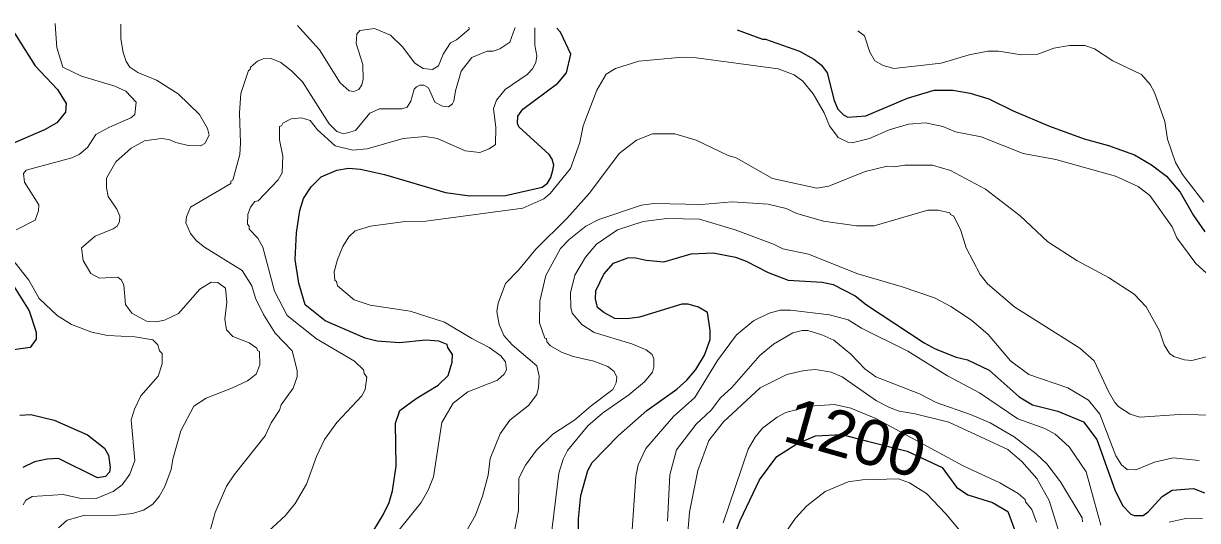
# Model space of a CAD drawing. Extents: x 598.3 to 623.2, y 6902.2 to 6930.1.
# Drawn here: x 609.703 to 611.773, y 6929.108 to 6929.984 of the extents above; entities that cross this region are included whole.
import ezdxf
from ezdxf.enums import TextEntityAlignment as Align

# ---------------------------------------------------------------- set-up
doc = ezdxf.new("R2010")
doc.units = 0
doc.header["$LTSCALE"] = 0.032
doc.layers.add('1', color=7, linetype='Continuous', lineweight=25)
doc.layers.add('2', color=7, linetype='Continuous', lineweight=13)
doc.layers.add('61', color=7, linetype='Continuous')

msp = doc.modelspace()

# ---------------------------------------------------------------- linework, layer by layer
at = {"layer": '1'}
for points in [[(609.6802, 6929.9779), (609.7233, 6929.9089), (609.763, 6929.8671), (609.7779, 6929.8425), (609.7771, 6929.8275), (609.7615, 6929.8085), (609.7397, 6929.7963), (609.6771, 6929.7691)], [(610.3103, 6929.0743), (610.3372, 6929.1179), (610.3473, 6929.1399), (610.3536, 6929.1605), (610.3601, 6929.2038), (610.3585, 6929.2792), (610.3663, 6929.302), (610.3951, 6929.3231), (610.4342, 6929.3461), (610.4514, 6929.3635), (610.4587, 6929.3868), (610.4594, 6929.4001), (610.4507, 6929.4128), (610.4498, 6929.4181), (610.4352, 6929.424), (610.4122, 6929.4257), (610.3656, 6929.421), (610.3263, 6929.4241), (610.3053, 6929.4289), (610.2348, 6929.4596), (610.1996, 6929.4881), (610.1884, 6929.5261), (610.182, 6929.5679), (610.1841, 6929.6148), (610.1901, 6929.6543), (610.1966, 6929.675), (610.2098, 6929.6956), (610.2278, 6929.7136), (610.2551, 6929.7253), (610.2758, 6929.7284), (610.2972, 6929.7268), (610.3392, 6929.7175), (610.4471, 6929.6856), (610.4898, 6929.6799), (610.5524, 6929.6807), (610.6174, 6929.6953), (610.6269, 6929.7021), (610.6327, 6929.7121), (610.636, 6929.7249), (610.6381, 6929.734), (610.6349, 6929.7443), (610.6294, 6929.7529), (610.576, 6929.8013), (610.5739, 6929.8081), (610.5746, 6929.8205), (610.5833, 6929.8326), (610.6446, 6929.8781), (610.6604, 6929.8964), (610.6675, 6929.9295), (610.6493, 6929.9684), (610.6431, 6929.9755)], [(610.9612, 6929.9726), (611.0055, 6929.9557), (611.0111, 6929.9558), (611.0706, 6929.9345), (611.0964, 6929.9207), (611.1097, 6929.9103), (611.1194, 6929.8966), (611.1319, 6929.8479), (611.1386, 6929.8324), (611.1482, 6929.8226), (611.1558, 6929.8184), (611.188, 6929.821), (611.2612, 6929.8521), (611.3084, 6929.866), (611.3414, 6929.866), (611.3716, 6929.8605), (611.4045, 6929.8506), (611.4475, 6929.8297), (611.5114, 6929.8028), (611.5726, 6929.7802), (611.6157, 6929.7683), (611.6613, 6929.752), (611.6911, 6929.7348), (611.7177, 6929.7145), (611.742, 6929.6862), (611.7652, 6929.645), (611.7851, 6929.6164)], [(610.6822, 6928.9996), (610.6814, 6929.1107), (610.6854, 6929.1518), (610.6977, 6929.1961), (610.7053, 6929.21), (610.752, 6929.2576), (610.802, 6929.3018), (610.8549, 6929.3392), (610.8722, 6929.3551), (610.888, 6929.3742), (610.9036, 6929.3991), (610.9136, 6929.4271), (610.9136, 6929.4433), (610.9087, 6929.4742), (610.8926, 6929.4839), (610.8748, 6929.4888), (610.8635, 6929.4888), (610.7887, 6929.4661), (610.7672, 6929.463), (610.7453, 6929.4638), (610.726, 6929.4742), (610.7148, 6929.4831), (610.7114, 6929.4983), (610.7117, 6929.5125), (610.7258, 6929.542), (610.7432, 6929.5611), (610.768, 6929.5706), (610.7793, 6929.5714), (610.8007, 6929.5665)], [(610.8007, 6929.5665), (610.8319, 6929.5634), (610.8797, 6929.5779), (610.9188, 6929.5795), (610.9581, 6929.572), (610.9771, 6929.5648), (611.0157, 6929.5447), (611.0507, 6929.5316), (611.1109, 6929.5278), (611.1303, 6929.5237), (611.1689, 6929.5038), (611.1889, 6929.488), (611.2909, 6929.4208), (611.3103, 6929.4103), (611.3473, 6929.3958), (611.3673, 6929.3908), (611.4053, 6929.3727), (611.4579, 6929.3258), (611.4817, 6929.3117), (611.5264, 6929.3008), (611.5718, 6929.2816), (611.5953, 6929.2508), (611.627, 6929.1621), (611.6405, 6929.1346), (611.6551, 6929.1193), (611.6609, 6929.1165), (611.6767, 6929.1168), (611.6853, 6929.1232), (611.71, 6929.1503), (611.7278, 6929.1616), (611.7653, 6929.1642), (611.7847, 6929.1569)], [(609.6834, 6929.5242), (609.7132, 6929.4775), (609.725, 6929.44), (609.7253, 6929.4276), (609.7148, 6929.4128), (609.6855, 6929.4088)], [(609.6962, 6929.2937), (609.7159, 6929.2945), (609.7569, 6929.2848), (609.8158, 6929.2591), (609.846, 6929.2355), (609.8525, 6929.223), (609.8557, 6929.2021), (609.8546, 6929.193), (609.8472, 6929.1857), (609.8336, 6929.183), (609.7645, 6929.2174), (609.7446, 6929.2162), (609.7221, 6929.2112), (609.7018, 6929.2011)], [(610.8897, 6928.9067), (610.9662, 6929.1082), (611.0002, 6929.1794), (611.031, 6929.2207), (611.0663, 6929.2429), (611.0989, 6929.2572), (611.1455, 6929.2594), (611.1906, 6929.2479), (611.2607, 6929.2301), (611.3226, 6929.2013), (611.3479, 6929.1666), (611.3677, 6929.1532), (611.411, 6929.1398), (611.4382, 6929.1237), (611.4576, 6929.0716)]]:
    msp.add_lwpolyline(points, dxfattribs=at)
at = {"layer": '2'}
for points in [[(609.7076, 6929.725), (609.7881, 6929.7467), (609.8013, 6929.7526), (609.8156, 6929.7653), (609.8302, 6929.7878), (609.8544, 6929.8011), (609.8919, 6929.8174), (609.8994, 6929.8233), (609.9016, 6929.8452), (609.8833, 6929.8644), (609.8637, 6929.8729), (609.805, 6929.8908), (609.7724, 6929.9067), (609.7615, 6929.9411), (609.7595, 6929.9738), (609.7589, 6929.9835)], [(609.8727, 6929.6443), (609.8674, 6929.6567), (609.8523, 6929.6788), (609.8493, 6929.6939), (609.8493, 6929.711), (609.8656, 6929.7397), (609.8929, 6929.7641), (609.9164, 6929.777), (609.9455, 6929.781), (609.959, 6929.7794), (609.9712, 6929.7738), (609.993, 6929.7686), (610.0149, 6929.7682), (610.0225, 6929.7722), (610.0304, 6929.787), (610.0272, 6929.7984), (610.0129, 6929.8231), (609.9753, 6929.8598), (609.9376, 6929.8837), (609.9046, 6929.8971), (609.8905, 6929.9067), (609.8841, 6929.9164), (609.8784, 6929.9322), (609.8744, 6929.9562), (609.8744, 6929.9803), (609.8744, 6929.9825)], [(610.5695, 6929.9762), (610.5663, 6929.9673), (610.5603, 6929.9506), (610.5429, 6929.9389), (610.5306, 6929.935), (610.5203, 6929.9348), (610.4933, 6929.9238), (610.4743, 6929.8998), (610.4644, 6929.8646), (610.4615, 6929.8469), (610.4593, 6929.8418), (610.4524, 6929.8367), (610.4413, 6929.8378), (610.4283, 6929.845), (610.4166, 6929.8701), (610.4085, 6929.8749), (610.4017, 6929.8748), (610.396, 6929.872), (610.3916, 6929.8677), (610.3859, 6929.8465), (610.3793, 6929.8362), (610.3697, 6929.8329), (610.3302, 6929.8329), (610.3133, 6929.8257), (610.288, 6929.7951), (610.2675, 6929.7892), (610.2551, 6929.793), (610.2418, 6929.807), (610.1945, 6929.8809), (610.1756, 6929.8999), (610.1563, 6929.9145), (610.1398, 6929.9219), (610.1252, 6929.9211), (610.1156, 6929.917), (610.1029, 6929.9068), (610.1024, 6929.9026), (610.0994, 6929.9008), (610.0863, 6929.8603), (610.0839, 6929.8263), (610.0856, 6929.7728), (610.084, 6929.753), (610.072, 6929.7073), (610.0687, 6929.7056), (610.0684, 6929.7017), (609.9976, 6929.6598), (609.9901, 6929.6428), (609.9893, 6929.6325), (609.9972, 6929.6138), (610.008, 6929.6005), (610.0218, 6929.5894), (610.0882, 6929.5485), (610.1057, 6929.5215), (610.1118, 6929.4997), (610.126, 6929.471), (610.1468, 6929.4381), (610.1768, 6929.4066), (610.1852, 6929.3721), (610.1851, 6929.3609), (610.1785, 6929.3413), (610.1574, 6929.3119), (610.1541, 6929.3022), (610.1397, 6929.2798), (610.1291, 6929.2571), (610.0741, 6929.1886), (610.0605, 6929.1683), (610.0407, 6929.1219), (610.0291, 6929.0798)], [(610.1205, 6929.076), (610.1641, 6929.1164), (610.1818, 6929.1381), (610.2016, 6929.1721), (610.2194, 6929.2207), (610.2337, 6929.2508), (610.2551, 6929.2805), (610.2994, 6929.3277), (610.3051, 6929.3389), (610.3082, 6929.3607), (610.3034, 6929.3669), (610.3023, 6929.3733), (610.2867, 6929.3886), (610.2197, 6929.4282), (610.1676, 6929.4692), (610.1455, 6929.5121), (610.1251, 6929.5895), (610.1163, 6929.6054), (610.101, 6929.6211), (610.1008, 6929.6265), (610.0978, 6929.6298), (610.0985, 6929.6473), (610.1032, 6929.6598), (610.1107, 6929.6699), (610.1164, 6929.6712), (610.1517, 6929.708), (610.1592, 6929.7205), (610.16, 6929.7497), (610.1545, 6929.7784), (610.1545, 6929.8019), (610.1576, 6929.8032), (610.1598, 6929.8081), (610.1746, 6929.8158), (610.1929, 6929.8175), (610.208, 6929.8124), (610.2211, 6929.7961), (610.2523, 6929.768), (610.2837, 6929.7601), (610.3088, 6929.7629), (610.3724, 6929.7809), (610.4112, 6929.7844), (610.4327, 6929.7811), (610.4814, 6929.7592), (610.5073, 6929.756), (610.5237, 6929.7626), (610.5348, 6929.7701), (610.5356, 6929.8), (610.5316, 6929.8339), (610.5366, 6929.8485), (610.5523, 6929.8673), (610.5909, 6929.8937), (610.6001, 6929.9038), (610.6061, 6929.9147), (610.6077, 6929.9266), (610.6045, 6929.9452), (610.6045, 6929.9656), (610.6045, 6929.9758)], [(610.1859, 6929.9797), (610.1899, 6929.9753), (610.225, 6929.9371), (610.2614, 6929.8789), (610.2768, 6929.8646), (610.2855, 6929.8637), (610.294, 6929.8673), (610.2994, 6929.8753), (610.3017, 6929.8853), (610.301, 6929.9112), (610.2896, 6929.9481), (610.2904, 6929.9647), (610.2961, 6929.9712), (610.3219, 6929.9745), (610.3498, 6929.9627), (610.3712, 6929.9423), (610.3925, 6929.9137), (610.4073, 6929.9041), (610.4239, 6929.9026), (610.4344, 6929.909), (610.4427, 6929.9295), (610.4558, 6929.9496), (610.4661, 6929.9545), (610.4883, 6929.9734), (610.4882, 6929.9769)], [(611.1737, 6929.9706), (611.1857, 6929.9615), (611.1947, 6929.9328), (611.2034, 6929.918), (611.2184, 6929.9096), (611.2373, 6929.9042), (611.3208, 6929.9136), (611.37, 6929.9284), (611.4029, 6929.9349), (611.4218, 6929.9349), (611.462, 6929.9285), (611.4908, 6929.9293), (611.5195, 6929.9398), (611.5466, 6929.9447), (611.5737, 6929.9446), (611.5907, 6929.9388), (611.6231, 6929.9177), (611.6736, 6929.8935), (611.6893, 6929.8763), (611.6966, 6929.8621), (611.715, 6929.811), (611.7197, 6929.7795), (611.7334, 6929.7389), (611.7458, 6929.7176), (611.7838, 6929.6687)], [(611.8136, 6929.5206), (611.7697, 6929.5605), (611.736, 6929.6057), (611.7279, 6929.6251), (611.6887, 6929.6804), (611.668, 6929.6961), (611.628, 6929.7146), (611.523, 6929.7437), (611.4652, 6929.7545), (611.3911, 6929.7836), (611.346, 6929.7924), (611.3233, 6929.8021), (611.2928, 6929.8086), (611.2632, 6929.8061), (611.2288, 6929.7962), (611.1944, 6929.7807), (611.1636, 6929.773), (611.1558, 6929.7744), (611.1388, 6929.7828), (611.124, 6929.8032), (611.1143, 6929.8259), (611.0952, 6929.8594), (611.0766, 6929.882), (611.0615, 6929.8933), (611.033, 6929.9034), (610.8848, 6929.9235), (610.8646, 6929.9243), (610.7878, 6929.917), (610.7463, 6929.9045), (610.7302, 6929.8945), (610.7137, 6929.8661), (610.6895, 6929.8032), (610.6839, 6929.7741), (610.6673, 6929.7279), (610.6315, 6929.6843), (610.6204, 6929.6749), (610.5832, 6929.658), (610.4119, 6929.6355), (610.3756, 6929.6345), (610.3147, 6929.6264), (610.2874, 6929.6183), (610.2764, 6929.6075), (610.266, 6929.5906), (610.2563, 6929.568), (610.2508, 6929.5461), (610.2516, 6929.5312), (610.2548, 6929.5288), (610.2564, 6929.5215), (610.2858, 6929.4968), (610.3138, 6929.4871), (610.3843, 6929.4767), (610.4453, 6929.4575), (610.4931, 6929.4284), (610.5238, 6929.4126), (610.5444, 6929.3983), (610.5525, 6929.3877), (610.5542, 6929.3734), (610.55, 6929.3657), (610.5385, 6929.3554), (610.4861, 6929.3349), (610.4606, 6929.3149), (610.4406, 6929.2806), (610.4255, 6929.1846), (610.4165, 6929.1616), (610.4039, 6929.1394), (610.3096, 6929.0224)], [(610.7837, 6929.778), (610.8117, 6929.7891), (610.8509, 6929.7891), (610.8886, 6929.7782), (610.9453, 6929.7507), (610.9593, 6929.7469), (611.023, 6929.7102), (611.1013, 6929.6937), (611.1228, 6929.6969), (611.1865, 6929.7228), (611.2257, 6929.7324), (611.2375, 6929.7309), (611.2567, 6929.7341), (611.3055, 6929.7341), (611.3371, 6929.7248), (611.399, 6929.6915), (611.4597, 6929.6446), (611.5086, 6929.5987), (611.5595, 6929.5659), (611.6153, 6929.5359), (611.6606, 6929.5067), (611.6817, 6929.4842), (611.7052, 6929.4422), (611.7137, 6929.4172), (611.7233, 6929.4023), (611.7308, 6929.3966), (611.7494, 6929.3909), (611.7623, 6929.3901), (611.7931, 6929.3974)], [(610.4643, 6929.0551), (610.4998, 6929.1176), (610.5122, 6929.1508), (610.522, 6929.188), (610.5253, 6929.217), (610.543, 6929.2604), (610.5601, 6929.285), (610.5931, 6929.3107), (610.6077, 6929.3297), (610.6109, 6929.3424), (610.6117, 6929.3621), (610.6077, 6929.3803), (610.5641, 6929.4176), (610.5499, 6929.434), (610.5414, 6929.453), (610.5374, 6929.4761), (610.5398, 6929.4907), (610.5527, 6929.5252), (610.5757, 6929.5491), (610.606, 6929.586), (610.6607, 6929.6398), (610.7006, 6929.6845), (610.7529, 6929.7546), (610.7837, 6929.778)], [(609.69, 6929.6201), (609.7236, 6929.637), (609.7293, 6929.6535), (609.7301, 6929.6639), (609.7045, 6929.704), (609.7028, 6929.7193), (609.7076, 6929.725)], [(610.569, 6929.0928), (610.5753, 6929.1256), (610.5761, 6929.1826), (610.5879, 6929.2055), (610.6073, 6929.2317), (610.6363, 6929.2599), (610.6746, 6929.2852), (610.7037, 6929.31), (610.7419, 6929.339), (610.7475, 6929.3506), (610.7486, 6929.3605), (610.744, 6929.3702), (610.733, 6929.3791), (610.7083, 6929.3886), (610.6719, 6929.3967), (610.6512, 6929.4044), (610.6318, 6929.4155), (610.6256, 6929.4226), (610.6247, 6929.4286), (610.6221, 6929.4294), (610.6126, 6929.4563), (610.6132, 6929.4944), (610.6236, 6929.5396), (610.6496, 6929.5869), (610.6646, 6929.6027), (610.6943, 6929.6266), (610.7172, 6929.6381), (610.7923, 6929.6637), (610.8143, 6929.6662), (610.8984, 6929.6646)], [(610.8984, 6929.6646), (610.9522, 6929.6694), (611.0155, 6929.6654), (611.0476, 6929.6574), (611.0663, 6929.6485), (611.1134, 6929.6355), (611.1715, 6929.6272), (611.2025, 6929.6273), (611.2972, 6929.6547), (611.3152, 6929.6548), (611.3358, 6929.6501), (611.3368, 6929.6472), (611.3427, 6929.6441), (611.3554, 6929.619), (611.3649, 6929.5884), (611.3894, 6929.5411), (611.4022, 6929.525), (611.4507, 6929.4835), (611.5649, 6929.4115), (611.5902, 6929.3892), (611.6155, 6929.335), (611.6267, 6929.3159), (611.6339, 6929.3082), (611.6538, 6929.2952), (611.6709, 6929.2898), (611.7405, 6929.2945), (611.8072, 6929.2938)], [(609.7644, 6929.0948), (609.7798, 6929.1086), (609.8112, 6929.1173), (609.8624, 6929.1165), (609.8952, 6929.1205), (609.9142, 6929.1259), (609.9308, 6929.1366), (609.9422, 6929.1502), (609.9518, 6929.1678), (609.9634, 6929.1977), (609.9664, 6929.2159), (609.9804, 6929.2657), (610.0031, 6929.3091), (610.0249, 6929.3237), (610.0716, 6929.3414), (610.098, 6929.3541), (610.1131, 6929.3659), (610.1196, 6929.3821), (610.1188, 6929.4057), (610.1155, 6929.4074), (610.1144, 6929.4114), (610.1005, 6929.4211), (610.0722, 6929.4319), (610.0609, 6929.4439), (610.0581, 6929.4627), (610.0614, 6929.4925), (610.0589, 6929.5175), (610.0456, 6929.5274), (610.0335, 6929.5281), (610.0135, 6929.5153), (609.9762, 6929.4727), (609.9514, 6929.4607), (609.9367, 6929.4581), (609.9197, 6929.4589), (609.894, 6929.4733), (609.8825, 6929.4887), (609.8799, 6929.5226), (609.8755, 6929.5313), (609.8692, 6929.5366), (609.8372, 6929.535), (609.8215, 6929.5428), (609.8082, 6929.566), (609.805, 6929.5885), (609.8291, 6929.6086), (609.8612, 6929.6215), (609.8678, 6929.6265), (609.8719, 6929.634), (609.8727, 6929.6443)], [(611.2503, 6929.5204), (611.1735, 6929.5427), (611.0867, 6929.5771), (611.0415, 6929.5864), (611.0249, 6929.5948), (610.9572, 6929.62), (610.8946, 6929.6386), (610.8371, 6929.6402), (610.7953, 6929.6345), (610.7502, 6929.6199), (610.7132, 6929.595), (610.6934, 6929.572), (610.6749, 6929.5404), (610.6669, 6929.5092), (610.6675, 6929.4834), (610.6702, 6929.4734), (610.6871, 6929.4531), (610.7087, 6929.4392), (610.7756, 6929.4194), (610.8004, 6929.4087), (610.8114, 6929.4001), (610.8142, 6929.3928), (610.8143, 6929.3785), (610.8118, 6929.3693), (610.7979, 6929.3521), (610.7703, 6929.3291), (610.7237, 6929.297), (610.6979, 6929.2747), (610.6618, 6929.2312), (610.6542, 6929.2161), (610.6467, 6929.1914), (610.632, 6929.0712)], [(609.7025, 6929.1358), (609.707, 6929.1438), (609.7184, 6929.1501), (609.7726, 6929.1537), (609.8072, 6929.1463), (609.8313, 6929.147), (609.8612, 6929.1592), (609.8769, 6929.1709), (609.8905, 6929.1893), (609.8994, 6929.2136), (609.893, 6929.2851), (609.8986, 6929.3043), (609.9098, 6929.3274), (609.9405, 6929.3623), (609.9472, 6929.3839), (609.9471, 6929.4019), (609.9425, 6929.4068), (609.9398, 6929.4175), (609.9309, 6929.4265), (609.8992, 6929.4313), (609.851, 6929.4337), (609.8231, 6929.4396), (609.7874, 6929.453), (609.762, 6929.4688), (609.7306, 6929.4989), (609.7121, 6929.5314), (609.6794, 6929.5728)], [(611.7756, 6929.2135), (611.7293, 6929.2184), (611.6966, 6929.2106), (611.6636, 6929.1975), (611.6483, 6929.1978), (611.6386, 6929.2059), (611.6285, 6929.2217), (611.6005, 6929.2954), (611.5805, 6929.3198), (611.5438, 6929.3414), (611.475, 6929.3654), (611.4426, 6929.389), (611.4035, 6929.4354), (611.3741, 6929.4607), (611.3376, 6929.485), (611.309, 6929.5), (611.2503, 6929.5204)], [(610.7744, 6929.0663), (610.7824, 6929.1852), (610.7867, 6929.2058), (610.7997, 6929.2348), (610.849, 6929.2913), (610.8863, 6929.3248), (610.9266, 6929.3901), (610.9597, 6929.4352), (610.9899, 6929.4597), (611.0175, 6929.4734), (611.0365, 6929.4783), (611.0548, 6929.4783), (611.124, 6929.4703), (611.1568, 6929.4612), (611.1803, 6929.447), (611.2621, 6929.4061), (611.3319, 6929.3628), (611.3879, 6929.3328), (611.4555, 6929.2871), (611.5036, 6929.27), (611.5214, 6929.2599), (611.5463, 6929.2375), (611.5765, 6929.1935), (611.6019, 6929.0998)], [(611.5695, 6929.1059), (611.5691, 6929.1125), (611.5307, 6929.1762), (611.5066, 6929.2076), (611.4879, 6929.2255), (611.4494, 6929.2554), (611.407, 6929.2799), (611.3726, 6929.2949), (611.3115, 6929.3159), (611.2823, 6929.3313), (611.2054, 6929.3608), (611.1863, 6929.3749), (611.1611, 6929.401), (611.1312, 6929.4259), (611.1105, 6929.4351), (611.0853, 6929.4427), (611.0754, 6929.4427), (611.0591, 6929.4384), (611.0252, 6929.4183), (611.0009, 6929.3988), (610.9515, 6929.3421), (610.9317, 6929.3238), (610.9149, 6929.3023), (610.8886, 6929.2775), (610.8541, 6929.2323), (610.8425, 6929.1883), (610.8384, 6929.1066)], [(610.8717, 6929.0585), (610.8772, 6929.1227), (610.8919, 6929.1961), (610.9111, 6929.249), (610.9367, 6929.2819), (611.0017, 6929.3414), (611.0485, 6929.3654), (611.0791, 6929.3724), (611.0989, 6929.3739), (611.1269, 6929.3692), (611.1463, 6929.3612), (611.2065, 6929.319), (611.2294, 6929.3069), (611.2466, 6929.3008), (611.275, 6929.2961), (611.3344, 6929.2809), (611.438, 6929.2332), (611.463, 6929.2116), (611.4892, 6929.182), (611.5109, 6929.143), (611.5305, 6929.0809)], [(611.4885, 6929.1049), (611.4804, 6929.1276), (611.4692, 6929.1408), (611.4687, 6929.145), (611.4562, 6929.1557), (611.424, 6929.1746), (611.3591, 6929.2042), (611.2054, 6929.2875), (611.1612, 6929.306), (611.1323, 6929.3123), (611.0885, 6929.3091), (611.0468, 6929.2984), (611.0313, 6929.2899), (611.0056, 6929.2706), (610.9928, 6929.2549), (610.9803, 6929.2336), (610.9364, 6929.1038)], [(611.3556, 6929.0873), (611.3288, 6929.1198), (611.2947, 6929.1555), (611.2648, 6929.1745), (611.2453, 6929.1812), (611.1822, 6929.1796), (611.1565, 6929.1763), (611.1159, 6929.1592), (611.084, 6929.1336), (611.0641, 6929.112), (611.0413, 6929.0795)], [(611.7227, 6929.1049), (611.7489, 6929.1108), (611.7813, 6929.1117)]]:
    msp.add_lwpolyline(points, dxfattribs=at)

# ---------------------------------------------------------------- texts
at = {"layer": '61', "width": 1.05}
msp.add_text('1200', height=0.08, rotation=344.249, dxfattribs=at).set_placement((611.1586, 6929.2153), align=Align.CENTER)

doc.saveas('drawing.dxf')
